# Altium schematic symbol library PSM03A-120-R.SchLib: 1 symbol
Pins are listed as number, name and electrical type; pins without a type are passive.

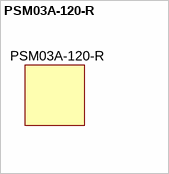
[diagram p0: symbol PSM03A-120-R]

## PSM03A-120-R
designator PS?
POWER SUPPLY WALL 12V 230MA 3W; Manufacturer: PHIHONG USA; SymbolVersion: use current date i.e. 2008-05-20; SymbolCreator: A0412036; CompType: Used in some BOM reports.  Useful for finding later.; U/M: EA; Cord Length: 59" (1.5m); Approvals: cULus; Output Connector: Barrel Plug, 2.1mm I.D. x 5.5mm O.D. x 10.0mm; Region Utilized: North America; Efficiency: Level V; Polarization: Positive Center; No Load Power Consumption: 150mW (Max); Input Type: Fixed Blade; Form: Wall Mount; Voltage - Input: 90 ~ 264 VAC
footprint PSMP03A-120-R (PHIHONG WALL WART 12V 230MA)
